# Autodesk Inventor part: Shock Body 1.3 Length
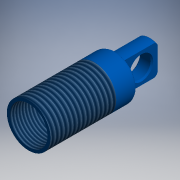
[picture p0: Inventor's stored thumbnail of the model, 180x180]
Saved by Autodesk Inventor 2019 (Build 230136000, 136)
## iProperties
Shininess: 28.0
Compacted: True
Length Units: 11272
Angle Units: 11279
Time Units: 11290
Mass Units: 11286
Length Display Precision: 4
Angle Display Precision: 2
Company: Autodesk
Created: 2000-03
Part Number: Shock Body 1.3 Length
Project: Inventor Samples
User Status: IN PROGRESS
Document SubType Name: Modeling
Designer: Autodesk, Inc.
Density: 1.13 g/cm^3
Mass: 1.29919 g
Surface Area: 23.4314 cm^2
Volume: 1.14973 cm^3
Material: Nylon-6/6
Appearance: Electric Blue
Density: 0.0
Volumn: 0.0
Area: 0.0
PropertySet Name: Model Information
Control State: 0
Master: False
Checked Out: False
Checked Out Date: 2018-05-30
Last Check In Date: 2018-05-30
Title: Shock Body 1.625 Length
Author: Autodesk, Inc.
Revision Number: A
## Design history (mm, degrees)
node "Extrusion1" dims "d1" = 25.4, "d2" = 0
  sketch "Sketch2"
    geometry: C1 r 6.35 at (-3.753, -1.332)
    constraints: 1 centre point
    dimensions: "d0" = 12.7 diameter of C1
workaxis "Work Axis1"
node "Shell1" dims "d17" = 0.889
node "Fillet2" dims "d18" = 1.27
node "Extrusion2" dims "d4" = 10.16, "d5" = 0
  sketch "Sketch3"
    geometry: C1 r 6.35 at (0, 0) reference; C2 r 4.763 at (0, 0)
    constraints: 1 centre point, 1 coincident
    dimensions: "d3" = 9.525 diameter of C2
node "Extrusion3" dims "d8" = 9.525, "d9" = 0
  sketch "Sketch4"
    geometry: L1 (-1.905, 4.365)-(-1.905, -4.365); L2 (1.905, 4.365)-(1.905, -4.365); A1 r 4.763 centre (0, 0) between (-1.905, 4.365) and (-1.905, -4.365) reference
    constraints: 4 end point, 4 point on circle, 1 parallel, 1 vertical
    dimensions: "d6" = 3.81 distance between parallel lines of L2 L1; "d7" = 1.905 distance from line of A1.centre L1 (= 0.5 x d6)
node "Extrusion4" dims "d13" = 9.525, "d14" = 0
  sketch "Sketch5"
    geometry: L1 (-9.525, 1.438)-(-9.525, 7.292) reference; L2 (-17.272, 4.365)-(32.512, 4.365) reference; C1 r 3.048 at (-5.397, 4.365)
    constraints: 1 centre point, 1 point on line
    dimensions: "d11" = 4.7625 distance from line of C1.centre L1; "d12" = 6.096 diameter of C1
node "Chamfer1" dims "d15" = 0.381, "d16" = 0.381, "d26" = 45 deg
node "Fillet3" dims "d19" = 1.27
thread "Thread1" dims "d20" = 19.05, "d21" = 0
thread "Thread2" dims "d22" = 9.525, "d23" = 0
sketch "Sketch6"
  geometry: C1 r 9.593 at (10.978, -0.3)
  constraints: 1 centre point
extrude "Extrusion5" cut sketch "Sketch6" stored distance "d24" = 25.4; taper "d25" = 0 deg
workplane "Work Plane1"
body "Solid1"
